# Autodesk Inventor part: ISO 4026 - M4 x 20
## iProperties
Comments: To add or edit properties for Autodesk Inventor files, use iProperties.
Created: 2004-08
Part Number: ISO 4026 - M4 x 20
Vendor: Autodesk Inc.
Document SubType Name: Modeling
Designer: John Blackburn
Material: Default
Description: Hexagon Socket Set Screw
Standard: ISO 4026
Alert: To add or edit properties for Autodesk Inventor files, use iProperties.
Control State: 0
Master: False
Checked Out: False
Shininess: 64.0
Length Units: 11269
Angle Units: 11279
Time Units: 11290
Mass Units: 11283
Length Display Precision: 3
Angle Display Precision: 2
Compacted: True
EGR: 1
Density: 0.0
Volumn: 0.0
Area: 0.0
PropertySet Name: Model Information
Author: John Blackburn
Revision Number: 8
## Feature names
1. Body [Revolution]
2. Chamfer1
3. Slot [Extrusion]
4. Chamfer2
